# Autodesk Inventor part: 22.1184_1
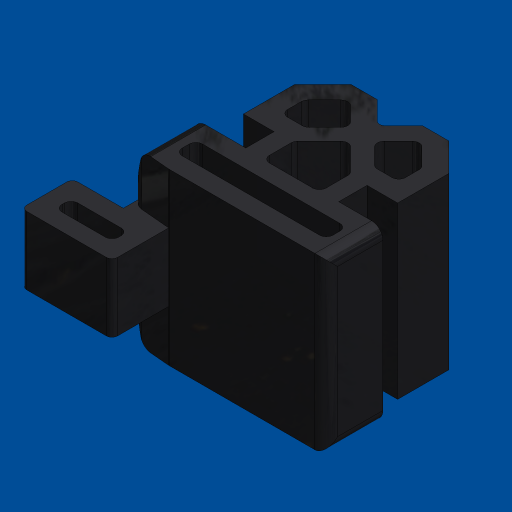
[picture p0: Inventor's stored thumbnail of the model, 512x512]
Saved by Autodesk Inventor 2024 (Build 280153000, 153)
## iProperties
Created: 2024-12
Part Number: 22.1184_1
Material: Polyethylene, High Density
Document SubType Name: Modeling
Designer: amoles
Appearance: Smooth - Off-White
Mass: 2.11711 g
Surface Area: 25.9148 cm^2
Volume: 2.22386 cm^3
Density: 0.952 g/cm^3
Sending System: MiniTec Maschinenbau GmbH & Co.KG
Major Version: 4.0
Minor Version: 0.0
Format Version: 0.0
Product Id: MiniTec Maschinenbau GmbH & Co.KG
Art.-Nr.: 22.1184/0
L: -
Stück: 1
5: Schiebetür-Führung 30V
7: 22.1184/0
8: MiniTec Maschinenbau GmbH & Co KG
Bestellnummer: 22.1184/0
Beschreibung: Schiebetür-Führung 30V
Länge: -
Artikelnr: 22.1184/0
Lieferant: MiniTec Maschinenbau GmbH & Co KG
Author: amoles
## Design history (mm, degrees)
feature "22_1_1:1"
sketch "Sketch1"
  geometry: C1 r 1.5 at (0, 0) reference
extrude "Extrusion1" cut sketch "Sketch1" distance "d0" = 7; taper "d1" = 0 deg
sketch "Sketch2"
  geometry: L1 (1.498, -0.082)-(0.354, 1.062) reference; L2 (-0.353, 1.062)-(-1.498, -0.082) reference; A1 r 1.5 centre (0, 0) between (1.498, -0.082) and (-1.498, -0.082) reference; A2 r 0.5 centre (0, 0.709) between (0.354, 1.062) and (-0.353, 1.062) reference
extrude "Extrusion2" join sketch "Sketch2" distance "d2" = 7; taper "d3" = 0 deg
body "Solid1"
